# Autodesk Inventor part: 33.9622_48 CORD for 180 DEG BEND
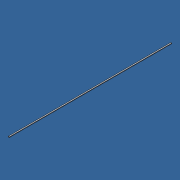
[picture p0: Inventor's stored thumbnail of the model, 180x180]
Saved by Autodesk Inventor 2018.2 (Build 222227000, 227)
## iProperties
Created: 2018-05
Part Number: 33.9622_48 CORD for 180 DEG BEND
Material: Generic
Document SubType Name: Modeling
Designer: amoles
Density: 1 g/cm^3
Appearance: White
Author: amoles
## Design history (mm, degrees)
sketch "Sketch1"
  geometry: L1 (-3.5, 1.65)-(3.5, 1.65); L2 (3.5, 1.65)-(3.5, -1.65); L3 (3.5, -1.65)-(-3.5, -1.65); L4 (-3.5, -1.65)-(-3.5, 1.65); 3 further points
  constraints: 8 end point, 2 midpoint, 2 parallel, 1 horizontal, 1 horizontal alignment, 1 perpendicular, 1 vertical alignment
  dimensions: "d0" = 7 distance of L1.start L1.end; "d1" = 3.3 distance of L1.end L2.end
extrude "Extrusion1" new body sketch "Sketch1" distance "d2" = 1034.288; taper "d3" = 0 deg
body "Solid1"
